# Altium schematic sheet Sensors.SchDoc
size 381 x 241 mm; SheetNumber: 3; SheetTotal: 6
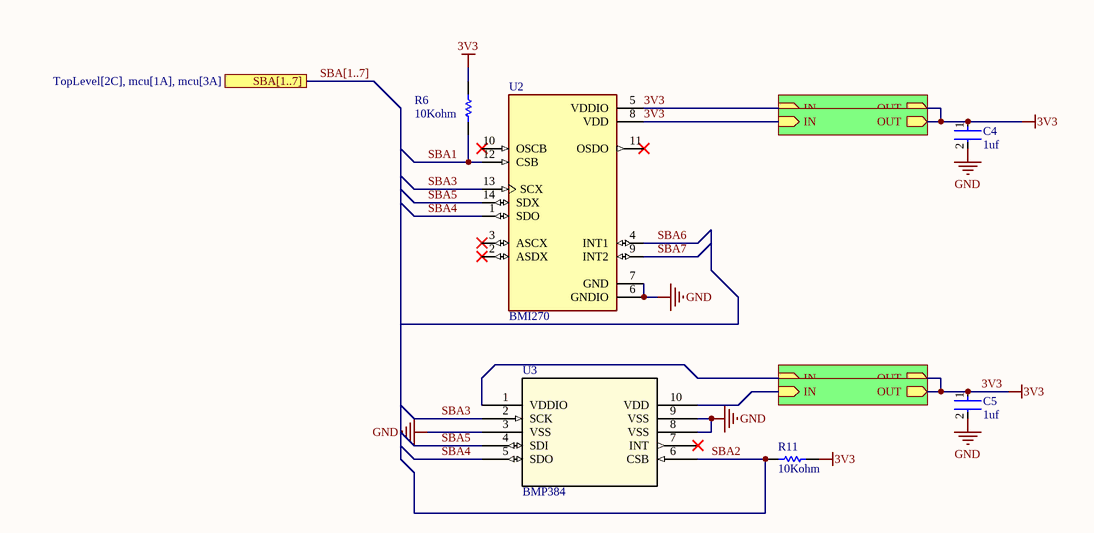
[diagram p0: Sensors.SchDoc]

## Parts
C4  1uf  [FP-CC0805-0_85-MFG]
C5  1uf  [FP-CC0805-0_85-MFG]
R6  10Kohm  [RESC2013X60X35ML10T20]
R11  10Kohm  [RESC2013X60X35ML10T20]
U2  BMI270  [XDCR_BMI270]
U3  BMP384  [LGA10_2.0X2.0X0.95_BOS]

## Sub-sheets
U_VDDCap = VDDCap.SchDoc: OUT (out), IN (in)
U_VDDCap = VDDCap.SchDoc: OUT (out), IN (in)
U_VDDCap = VDDCap.SchDoc: OUT (out), IN (in)
U_VDDCap = VDDCap.SchDoc: OUT (out), IN (in)

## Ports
SBA[1..7] (see TopLevel[2C], mcu[1A], mcu[3A])

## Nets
3V3: C4.1 C5.1 R6.1 R11.1 U2.5(VDDIO) U2.8(VDD) ; sheet U_VDDCap/OUT, sheet U_VDDCap/IN, sheet U_VDDCap/OUT, sheet U_VDDCap/IN, sheet U_VDDCap/OUT, sheet U_VDDCap/OUT
GND: C4.2 C5.2 U2.6(GNDIO) U2.7(GND) U3.3(VSS) U3.8(VSS) U3.9(VSS)
SBA1: R6.2 U2.12(CSB)
SBA2: R11.2 U3.6(CSB)
SBA3: U2.13(SCX) U3.2(SCK)
SBA4: U2.1(SDO) U3.5(SDO)
SBA5: U2.14(SDX) U3.4(SDI)
SBA6: U2.4(INT1)
SBA7: U2.9(INT2)
NetU3_1: U3.1(VDDIO) ; sheet U_VDDCap/IN
NetU3_10: U3.10(VDD) ; sheet U_VDDCap/IN

Not connected (* = marked no-connect by the designer): U2 2(ASDX)* 3(ASCX)* 10(OSCB)* 11(OSDO)*; U3 7(INT)*

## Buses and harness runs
bus SBA[1..7] = port SBA[1..7]

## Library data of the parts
C4 C5 = CMP-2100-03605-2: CAP CER 1UF 25V X7R 0805; Manufacturer Part Number: CC0805KKX7R8BB105; Manufacturer: Yageo; Material: Ceramic; Tolerance: 0.1
R6 R11 = CMP-2000-05025-1: Chip Resistor, 10 KOhm, +/- 5%, 0.125 W, -55 to 155 degC, 0805 (2012 Metric), RoHS, Tape and Reel; Manufacturer: Yageo; Resistor Element Type: ThickFilm; Voltage Rating: 150V; Product Range: RCSeries; SVHC: ToBeAdvised; Resistor Case Style: 0805[2012Metric]; Temperature Coefficient: ±100ppm/degC; Power Rating: 250mW
U2 = BMI270: Accelerometer, Gyroscope, 6 Axis Sensor IÂ²C, SPI Output; MF: Bosch Sensortec
U3 = BMP384: Description; Manufacturer_Name: Bosch Sensortec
